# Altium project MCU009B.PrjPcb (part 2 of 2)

## Sheet MCU009B_Xds100v2Emu.SchDoc: Xds100v2Emu
size 431 x 279 mm; Date: Not shown in title block; ApprovedBy: Not shown in title block; CheckedBy: Not shown in title block; Author: Not shown in title block; CompanyName: Not shown in title block; Engineer: Not shown in title block; Organization: Not shown in title block; Address1: Not shown in title block; Address2: Not shown in title block; Address3: Not shown in title block; Address4: Not shown in title block; DocumentNumber: 5; Revision: Use project parameter SCH_Rev; SheetNumber: 5; SheetTotal: 7; PageSetup: Record=PageOptions¦CenterHorizontal=True¦CenterVertical=True¦PrintScale=1.00¦XCorrection=1.00¦YCorrection=1.00¦PrintKind=0¦BorderSize=5000000¦LeftOffset=0¦BottomOffset=0¦Orientation=2¦PaperLength=1000¦PaperWidth=1000¦Scale=100¦PaperSource=15¦PrintQuality=600¦MediaType=1¦DitherType=10¦PaperKind=Letter¦PrintScaleMode=1
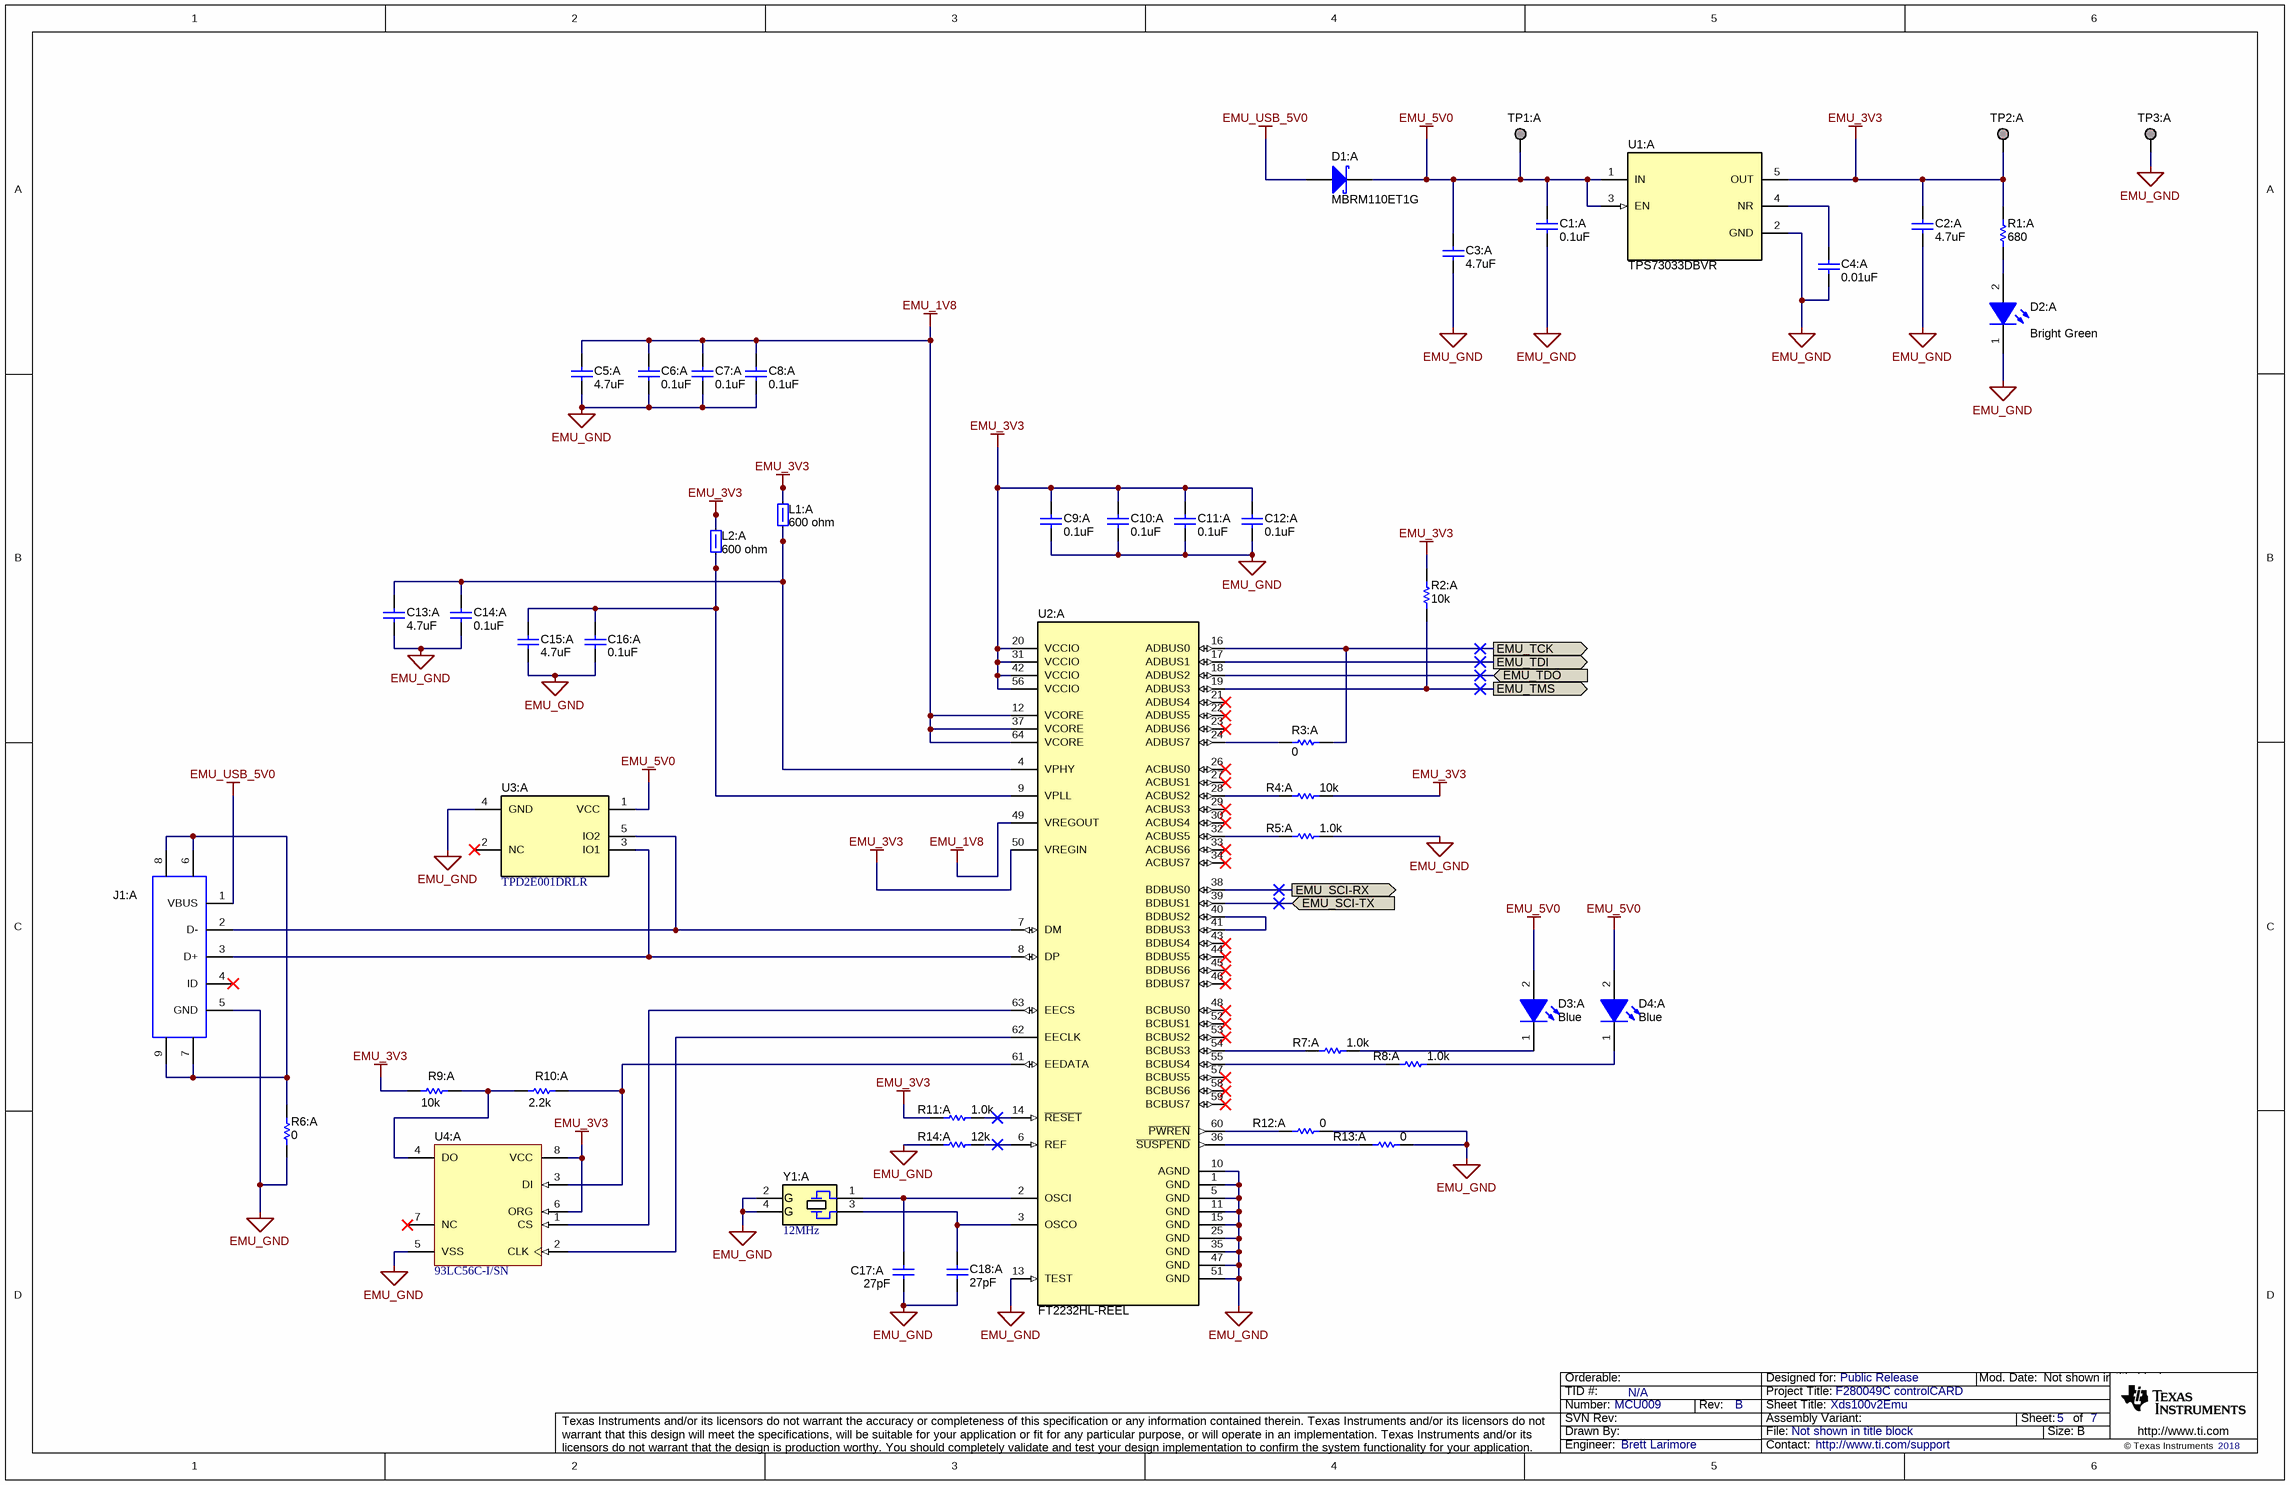
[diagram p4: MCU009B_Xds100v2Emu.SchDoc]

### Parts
C1:A  ValueDisplayed: 0.1uF  [0402]  (hidden comment: GRM155R71A104KA01D)
C2:A  ValueDisplayed: 4.7uF  [0603]  (hidden comment: GRM188R60J475ME19D)
C3:A  ValueDisplayed: 4.7uF  [0603]  (hidden comment: GRM188R60J475ME19D)
C4:A  ValueDisplayed: 0.01uF  [0402]  (hidden comment: GRM155R71C103KA01D)
C5:A  ValueDisplayed: 4.7uF  [0603]  (hidden comment: GRM188R60J475ME19D)
C6:A  ValueDisplayed: 0.1uF  [0402]  (hidden comment: GRM155R71A104KA01D)
C7:A  ValueDisplayed: 0.1uF  [0402]  (hidden comment: GRM155R71A104KA01D)
C8:A  ValueDisplayed: 0.1uF  [0402]  (hidden comment: GRM155R71A104KA01D)
C9:A  ValueDisplayed: 0.1uF  [0402]  (hidden comment: GRM155R71A104KA01D)
C10:A  ValueDisplayed: 0.1uF  [0402]  (hidden comment: GRM155R71A104KA01D)
C11:A  ValueDisplayed: 0.1uF  [0402]  (hidden comment: GRM155R71A104KA01D)
C12:A  ValueDisplayed: 0.1uF  [0402]  (hidden comment: GRM155R71A104KA01D)
C13:A  ValueDisplayed: 4.7uF  [0603]  (hidden comment: GRM188R60J475ME19D)
C14:A  ValueDisplayed: 0.1uF  [0402]  (hidden comment: GRM155R71A104KA01D)
C15:A  ValueDisplayed: 4.7uF  [0603]  (hidden comment: GRM188R60J475ME19D)
C16:A  ValueDisplayed: 0.1uF  [0402]  (hidden comment: GRM155R71A104KA01D)
C17:A  ValueDisplayed: 27pF  [0402]  (hidden comment: GRM1555C1H270JA01D)
C18:A  ValueDisplayed: 27pF  [0402]  (hidden comment: GRM1555C1H270JA01D)
D1:A  MBRM110ET1G  [POWERMITE]
D2:A  value Bright Green  [WL-SMCW_Green_0805]  (hidden comment: 150080VS75000)
D3:A  value Blue  [WL-SMCW_Blue_0805]  (hidden comment: 150080BS75000)
D4:A  value Blue  [WL-SMCW_Blue_0805]  (hidden comment: 150080BS75000)
J1:A  65100516121  [Wurth_65100516121]  (value not drawn)
L1:A  value 600 ohm  [0805_HV]  (hidden comment: HZ0805E601R-10)
L2:A  value 600 ohm  [0805_HV]  (hidden comment: HZ0805E601R-10)
R1:A  ValueDisplayed: 680  [0402]  (hidden comment: CRCW0402680RJNED)
R2:A  ValueDisplayed: 10k  [0402]  (hidden comment: CRCW040210K0JNED)
R3:A  ValueDisplayed: 0  [0402]  (hidden comment: CRCW04020000Z0ED)
R4:A  ValueDisplayed: 10k  [0402]  (hidden comment: CRCW040210K0JNED)
R5:A  ValueDisplayed: 1.0k  [0402]  (hidden comment: CRCW04021K00JNED)
R6:A  ValueDisplayed: 0  [0402]  (hidden comment: CRCW04020000Z0ED)
R7:A  ValueDisplayed: 1.0k  [0402]  (hidden comment: CRCW04021K00JNED)
R8:A  ValueDisplayed: 1.0k  [0402]  (hidden comment: CRCW04021K00JNED)
R9:A  ValueDisplayed: 10k  [0402]  (hidden comment: CRCW040210K0JNED)
R10:A  ValueDisplayed: 2.2k  [0402]  (hidden comment: CRCW04022K20JNED)
R11:A  ValueDisplayed: 1.0k  [0402]  (hidden comment: CRCW04021K00JNED)
R12:A  ValueDisplayed: 0  [0402]  (hidden comment: CRCW04020000Z0ED)
R13:A  ValueDisplayed: 0  [0402]  (hidden comment: CRCW04020000Z0ED)
R14:A  ValueDisplayed: 12k  [0402]  (hidden comment: CRCW040212K0JNED)
TP1:A  TESTPOINT  [TP_50MIL-25MILHOLE]  (value not drawn)  (no BOM)
TP2:A  TESTPOINT  [TP_50MIL-25MILHOLE]  (value not drawn)  (no BOM)
TP3:A  TESTPOINT  [TP_50MIL-25MILHOLE]  (value not drawn)  (no BOM)
U1:A  TPS73033DBVR  [DBV0005A_N]
U2:A  FT2232HL-REEL  [LQFP64_N]
U3:A  TPD2E001DRLR  [DRL0005A]
U4:A  93LC56C-I/SN  [SOIC-8]
Y1:A  12MHz  [ECS_ECX-53B]

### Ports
EMU_SCI-RX (out), EMU_SCI-TX (in), EMU_TCK (out), EMU_TDI (out), EMU_TDO (in), EMU_TMS (out)

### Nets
EMU_1V8: C5:A.2 C6:A.2 C7:A.2 C8:A.2 U2:A.12(VCORE) U2:A.37(VCORE) U2:A.49(VREGOUT) U2:A.64(VCORE)
EMU_3V3: C2:A.1 C9:A.2 C10:A.2 C11:A.2 C12:A.2 L1:A.2 L2:A.2 R1:A.1 R2:A.2 R4:A.2 R9:A.1 R11:A.1 TP2:A.1 U1:A.5(OUT) U2:A.20(VCCIO) U2:A.31(VCCIO) U2:A.42(VCCIO) U2:A.50(VREGIN) U2:A.56(VCCIO) U4:A.6(ORG) U4:A.8(VCC)
EMU_5V0: C1:A.2 C3:A.1 D1:A.1(K) D3:A.2(A) D4:A.2(A) TP1:A.1 U1:A.1(IN) U1:A.3(EN) U3:A.1(VCC)
EMU_GND: C1:A.1 C2:A.2 C3:A.2 C4:A.1 C5:A.1 C6:A.1 C7:A.1 C8:A.1 C9:A.1 C10:A.1 C11:A.1 C12:A.1 C13:A.2 C14:A.1 C15:A.2 C16:A.1 C17:A.1 C18:A.1 D2:A.1(K) J1:A.5(GND) R5:A.2 R6:A.2 R12:A.1 R13:A.1 R14:A.1 TP3:A.1 U1:A.2(GND) U2:A.1(GND) U2:A.5(GND) U2:A.10(AGND) U2:A.11(GND) U2:A.13(TEST) U2:A.15(GND) U2:A.25(GND) U2:A.35(GND) U2:A.47(GND) U2:A.51(GND) U3:A.4(GND) U4:A.5(VSS) Y1:A.2(GND) Y1:A.4(GND)
EMU_USB_5V0: D1:A.2(A) J1:A.1(VBUS)
EMU_SCI-RX: U2:A.38(BDBUS0) ; port EMU_SCI-RX
EMU_SCI-TX: U2:A.39(BDBUS1) ; port EMU_SCI-TX
EMU_TCK: R3:A.1 U2:A.16(ADBUS0) ; port EMU_TCK
EMU_TDI: U2:A.17(ADBUS1) ; port EMU_TDI
EMU_TDO: U2:A.18(ADBUS2) ; port EMU_TDO
EMU_TMS: R2:A.1 U2:A.19(ADBUS3) ; port EMU_TMS
NetC4:A_2: C4:A.2 U1:A.4(NR)
NetC13:A_1: C13:A.1 C14:A.2 L1:A.1 U2:A.4(VPHY)
NetC15:A_1: C15:A.1 C16:A.2 L2:A.1 U2:A.9(VPLL)
NetC17:A_2: C17:A.2 U2:A.2(OSCI) Y1:A.1
NetC18:A_2: C18:A.2 U2:A.3(OSCO) Y1:A.3
NetD2:A_2: D2:A.2(A) R1:A.2
NetD3:A_1: D3:A.1(K) R7:A.2
NetD4:A_1: D4:A.1(K) R8:A.2
NetJ1:A_2: J1:A.2(D-) U2:A.7(DM) U3:A.5(IO2)
NetJ1:A_3: J1:A.3(D+) U2:A.8(DP) U3:A.3(IO1)
NetJ1:A_6: J1:A.6 J1:A.7 J1:A.8 J1:A.9 R6:A.1
NetR3:A_2: R3:A.2 U2:A.24(ADBUS7)
NetR4:A_1: R4:A.1 U2:A.28(ACBUS2)
NetR5:A_1: R5:A.1 U2:A.32(ACBUS5)
NetR7:A_1: R7:A.1 U2:A.54(BCBUS3)
NetR8:A_1: R8:A.1 U2:A.55(BCBUS4)
NetR9:A_2: R9:A.2 R10:A.1 U4:A.4(DO)
NetR10:A_2: R10:A.2 U2:A.61(EEDATA) U4:A.3(DI)
NetR11:A_2: R11:A.2 U2:A.14(~{RESET})
NetR12:A_2: R12:A.2 U2:A.60(~{PWREN})
NetR13:A_2: R13:A.2 U2:A.36(~{SUSPEND})
NetR14:A_2: R14:A.2 U2:A.6(REF)
NetU2:A_40: U2:A.40(BDBUS2) U2:A.41(BDBUS3)
NetU2:A_62: U2:A.62(EECLK) U4:A.2(CLK)
NetU2:A_63: U2:A.63(EECS) U4:A.1(CS)

Not connected (* = marked no-connect by the designer): J1:A 4(ID)*; U2:A 21(ADBUS4)* 22(ADBUS5)* 23(ADBUS6)* 26(ACBUS0)* 27(ACBUS1)* 29(ACBUS3)* 30(ACBUS4)* 33(ACBUS6)* 34(ACBUS7)* 43(BDBUS4)* 44(BDBUS5)* 45(BDBUS6)* 46(BDBUS7)* 48(BCBUS0)* 52(BCBUS1)* 53(BCBUS2)* 57(BCBUS5)* 58(BCBUS6)* 59(BCBUS7)*; U3:A 2(NC)*; U4:A 7(NC)*

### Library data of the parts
C1:A C6:A C7:A C8:A C9:A C10:A C11:A C12:A C14:A C16:A = CMP-0006629-2: CAP, CERM, 0.1 uF, 10 V, +/- 10%, X7R, 0402; Manufacturer: MuRata; Polarized: N; Value: 0.1uF; U/M: EA; Cap_F: 100nF; Value1: Unknown; VDC_V: 10V; TaMin_C: -55°C; TaMax_C: 125°C; AEC Category: Q200; SizeArea_mm2: 0.5; SizeAreaWB_mm2: 3; SizeX_mm: 1; SizeZ_mm: 0.6
C2:A C3:A C5:A C13:A C15:A = CMP-0007312-5: CAP, CERM, 4.7 uF, 6.3 V, +/- 20%, X5R, 0603; Manufacturer: MuRata; Polarized: N; Value: 4.7uF; U/M: EA; Cap_F: 4.7µF; ESR_ohm: 1m; Value1: 0.001 ohm; VDC_V: 6.3V; TaMin_C: -55°C; TaMax_C: 85°C; AEC Category: Q200; SizeArea_mm2: 1.28; SizeAreaWB_mm2: 4.68; SizeX_mm: 1.6; SizeY_mm: 0.8; SizeZ_mm: 1
C4:A = CMP-0006639-2: CAP, CERM, 0.01 uF, 16 V, +/- 10%, X7R, 0402; Manufacturer: MuRata; Polarized: N; Value: 0.01uF; U/M: EA; Cap_F: 10nF; Value1: Unknown; VDC_V: 16V; TaMin_C: -55°C; TaMax_C: 125°C; AEC Category: Q200; SizeArea_mm2: 0.5; SizeAreaWB_mm2: 3; SizeX_mm: 1; SizeZ_mm: 0.6
C17:A C18:A = CMP-0006443-2: CAP, CERM, 27 pF, 50 V, +/- 5%, C0G/NP0, 0402; Manufacturer: MuRata; Polarized: N; Value: 27pF; U/M: EA; Value1: Unknown; VDC_V: 50V; TaMin_C: -55°C; TaMax_C: 125°C; AEC Category: Q200; SizeArea_mm2: 0.5; SizeAreaWB_mm2: 3; SizeX_mm: 1; SizeZ_mm: 0.6
D1:A = CMP-0028747-1: Diode, Schottky, 10 V, 1 A, AEC-Q101, POWERMITE; Manufacturer: ON Semiconductor; U/M: EA; Vf_V: 5.3dV; Value: 10V; Value1: 1A; Value2: 0.53V; TJmax_C: 150°C; AEC Category: Q101; AEC Qualified: Y; SizeAreaWB_mm2: 14.945; SizeArea_mm2: 7.995; SizeX_mm: 3.9; SizeY_mm: 2.05; SizeZ_mm: 1.15; Green_Lifecycle: Not Set; Green_REACh: Incomplete
D2:A = CMP-0002960-2: LED, Bright Green, SMD; Manufacturer: Wurth Elektronik; Type: AlInGaP; Vf_V: 2V; Io_A: 20mA; Vr_V: 5V; Tjmax_C: 85°C; Power_TotalModule: 72mW; Value1: 0.072W; Angle: 140; U/M: EA
D3:A D4:A = CMP-0002959-2: LED, Blue, SMD; Manufacturer: Wurth Elektronik; Type: InGaN; Vf_V: 3.2V; Io_A: 20mA; Vr_V: 5V; Tjmax_C: 85°C; Power_TotalModule: 105mW; Value1: 0.105W; Angle: 140; U/M: EA
J1:A = CMP-0054809-1: Connector, Receptacle, USB Mini B 2.0, SMT; Manufacturer: Wurth Elektronik; Pitch_mm: 0.8; Gender: Female; Row_Count: 1; ContactFinish: Gold; Current_A: 1A; Voltage_V: 30V; Cert_UL: Y; CNHeader: FALSE; CT: TRUE; Green_Lifecycle: Active; Green_REACh: Passed
L1:A L2:A = CMP-0003398-1: Ferrite Bead, 600 ohm @ 100 MHz, 0.5 A, 0805; Manufacturer: Laird-Signal Integrity Products; Imax_A: 5dA; DCR_ohm: 3d; Value1: 0.3 ohm; Value2: 0.5A; ZTyp@100MHz_Ohm: 600; SizeArea_mm2: 2.5; SizeAreaWB_mm2: 6.75; SizeX_mm: 2; SizeY_mm: 1.25; SizeZ_mm: 1.45
R1:A = CMP-0026962-3: RES, 680, 5%, 0.063 W, AEC-Q200 Grade 0, 0402; Manufacturer: Vishay-Dale; Value: 680; Value_Code: 680R; Power_W: 63mW; Value2: 0.063W; VDC_V: 50V; TempCo: 200 ppm/C; EIA_Code: E24; AEC Category: Q200; AEC Qualified: Y; AEC Grade: 0; SizeArea_mm2: 0.5; SizeX_mm: 1; SizeZ_mm: 0.6
R2:A R4:A R9:A = CMP-0026825-5: RES, 10 k, 5%, 0.063 W, AEC-Q200 Grade 0, 0402; Manufacturer: Vishay-Dale; Value: 10k; Value_Code: 10k0; Power_W: 63mW; Value2: 0.063W; VDC_V: 50V; TempCo: 200 ppm/C; EIA_Code: E24; AEC Category: Q200; AEC Qualified: Y; AEC Grade: 0; SizeArea_mm2: 0.5; SizeX_mm: 1; SizeZ_mm: 0.6
R3:A R6:A R12:A R13:A = CMP-0026822-3: RES, 0, 5%, 0.063 W, AEC-Q200 Grade 0, 0402; Manufacturer: Vishay-Dale; Value: 0; Value_Code: 0000; Power_W: 63mW; Value2: 0.063W; VDC_V: 50V; TempCo: 200 ppm/C; EIA_Code: E24; AEC Category: Q200; AEC Qualified: Y; SizeArea_mm2: 0.5; SizeX_mm: 1; SizeZ_mm: 0.6
R5:A R7:A R8:A R11:A = CMP-0026852-3: RES, 1.0 k, 5%, 0.063 W, AEC-Q200 Grade 0, 0402; Manufacturer: Vishay-Dale; Value: 1.0k; Res_ohm: 1k; Value_Code: 1k00; Power_W: 63mW; Value2: 0.063W; VDC_V: 50V; TempCo: 200 ppm/C; EIA_Code: E24; AEC Category: Q200; AEC Qualified: Y; AEC Grade: 0; SizeArea_mm2: 0.5; SizeX_mm: 1; SizeZ_mm: 0.6
R10:A = CMP-0026890-5: RES, 2.2 k, 5%, 0.063 W, AEC-Q200 Grade 0, 0402; Manufacturer: Vishay-Dale; Value: 2.2k; Value_Code: 2k20; Power_W: 63mW; Value2: 0.063W; VDC_V: 50V; TempCo: 200 ppm/C; EIA_Code: E24; AEC Category: Q200; AEC Qualified: Y; AEC Grade: 0; SizeArea_mm2: 0.5; SizeX_mm: 1; SizeZ_mm: 0.6
R14:A = CMP-0026834-3: RES, 12 k, 5%, 0.063 W, AEC-Q200 Grade 0, 0402; Manufacturer: Vishay-Dale; Value: 12k; Value_Code: 12k0; Power_W: 63mW; Value2: 0.063W; VDC_V: 50V; TempCo: 200 ppm/C; EIA_Code: E24; AEC Category: Q200; AEC Qualified: Y; AEC Grade: 0; SizeArea_mm2: 0.5; SizeX_mm: 1; SizeZ_mm: 0.6
TP1:A TP2:A TP3:A = CMP-0078143-2: TEST POINT.  No entry in BOM.
U1:A = CMP-0073823-1: Low-Noise, High PSRR, RF 200-mA Low-Dropout Linear Regulators, DBV0005A (SOT-23-5); Alternate PartNumber: TPS73033DBVT; Manufacturer: Texas Instruments; CompType: IC; U/M: EA; SizeArea_mm2: 8.12; SizeAreaWB_mm2: 14.82; SizeX_mm: 2.8; SizeY_mm: 2.9; SizeZ_mm: 1.45; Green_Lifecycle: Active; Green_REACh: Passed
U2:A = CMP-0004796-1: Dual High Speed USB To Multipurpose UART/FIFO IC, LQFP-64; Manufacturer: FTDI
U3:A = CMP-0043096-2: Low-Capacitance + / - 15 kV ESD-Protection Array for High-Speed Data Interfaces, 2 Channels, -40 to +85 degC, 5-pin SOT (DRL), Green (RoHS & no Sb/Br); Manufacturer: Texas Instruments; Breakdown Voltage(Min)(V): 11; IEC 61000-4-2 Air-Gap(+/- kV): 15; IEC 61000-4-2 Contact(+/- kV): 8; IO Capacitance(Typ)(pF): 1.5; IO Leakage Current(nA): 1; SubFamily: ESD Solution; USB High Speed: TRUE
U4:A = CMP-0005261-2: 2K Microwire Compatible Serial EEPROM, SOIC-8; Manufacturer: Microchip; SizeAreaWB_mm2: 55.131; SizeArea_mm2: 29.351; SizeX_mm: 5.99; SizeY_mm: 4.9; SizeZ_mm: 1.75
Y1:A = CMP-0004646-3: Crystal, 12 MHz, 20pF, SMD; PartNumber: ECS-120-20-30B-TR; Manufacturer: ECS Inc.; TaMin_C: -20°C; TaMax_C: 70°C; Frequency Stability: +/-50ppm

## Sheet MCU009B_EVM_Hardware.SchDoc: EVM Hardware
size 431 x 279 mm; Date: Not shown in title block; ApprovedBy: Not shown in title block; CheckedBy: Not shown in title block; Author: Not shown in title block; CompanyName: Not shown in title block; Engineer: Not shown in title block; Organization: Not shown in title block; Address1: Not shown in title block; Address2: Not shown in title block; Address3: Not shown in title block; Address4: Not shown in title block; DocumentNumber: 7; Revision: Use project parameter SCH_Rev; SheetNumber: 7; SheetTotal: 7; PageSetup: Record=PageOptions¦CenterHorizontal=True¦CenterVertical=True¦PrintScale=1.00¦XCorrection=1.00¦YCorrection=1.00¦PrintKind=0¦BorderSize=5000000¦LeftOffset=0¦BottomOffset=0¦Orientation=2¦PaperLength=1000¦PaperWidth=1000¦Scale=100¦PaperSource=15¦PrintQuality=600¦MediaType=1¦DitherType=10¦PaperKind=Letter¦PrintScaleMode=1
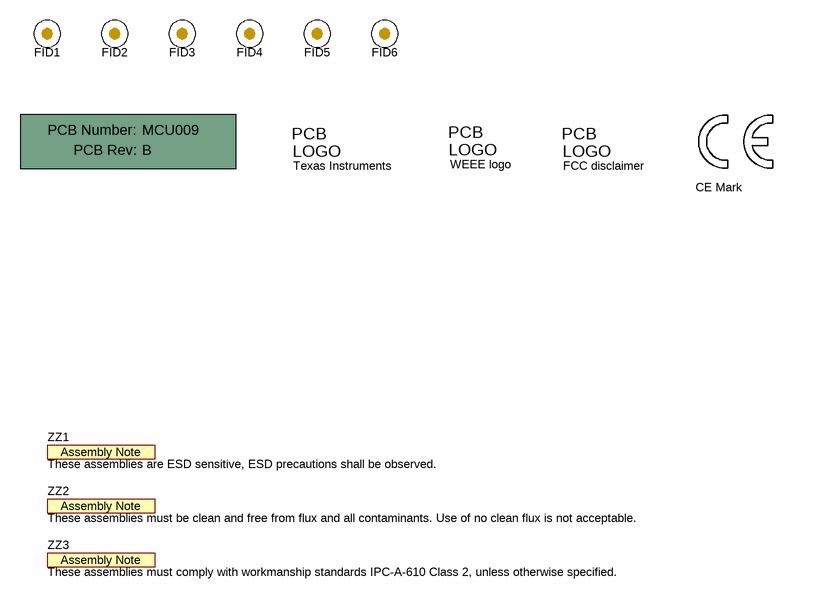
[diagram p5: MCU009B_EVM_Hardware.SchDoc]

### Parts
!PCB1  Printed Circuit Board  (value not drawn)  (mechanical)
FID1  Fiducial  [Fiducial10-20]  (value not drawn)
FID2  Fiducial  [Fiducial10-20]  (value not drawn)
FID3  Fiducial  [Fiducial10-20]  (value not drawn)
FID4  Fiducial  [Fiducial10-20]  (value not drawn)
FID5  Fiducial  [Fiducial10-20]  (value not drawn)
FID6  Fiducial  [Fiducial10-20]  (value not drawn)
Logo1  Texas Instruments  [TI_Symbol_Overlay_Small]  (no BOM)
Logo2  WEEE logo  [WEEE_Minimum]  (no BOM)
Logo3  FCC disclaimer  [FCC_disclaimer]  (no BOM)
LOGO4  CE Mark  [CE_Mark_5mm]  (no BOM)
ZZ1  These assemblies are ESD sensitive, ESD precautions shall be observed.  [AssemblyNote]  (no BOM)
ZZ2  These assemblies must be clean and free from flux and all contaminants. Use of no clean flux is not acceptable.  [AssemblyNote]  (no BOM)
ZZ3  These assemblies must comply with workmanship standards IPC-A-610 Class 2, unless otherwise specified.  [AssemblyNote]  (no BOM)

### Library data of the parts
!PCB1 = CMP-0003618-2: Manufacturer: Any; PartNumber: MCU009
FID1-FID6 = CMP-0077181-1: Fiducial mark.  There is nothing to buy or mount.
Logo1 = CMP-0074838-1: Texas Instrument Corporate Signature; SymbolCreator: a0412235; Lib Reference: TI_Logo
Logo2 = CMP-0074769-1
Logo3 = CMP-0074847-1: FCC_disclaimer
LOGO4 = CMP-0074844-1: SymbolCreator: a0412235
ZZ1 = CMP-0077236-1
ZZ2 = CMP-0077237-1
ZZ3 = CMP-0077238-1

## Sheet MCU009B_EmuInterface.SchDoc: EmuInterface
size 431 x 279 mm; Date: Not shown in title block; ApprovedBy: Not shown in title block; CheckedBy: Not shown in title block; Author: Not shown in title block; CompanyName: Not shown in title block; Engineer: Not shown in title block; Organization: Not shown in title block; Address1: Not shown in title block; Address2: Not shown in title block; Address3: Not shown in title block; Address4: Not shown in title block; DocumentNumber: 6; Revision: Use project parameter SCH_Rev; SheetNumber: 6; SheetTotal: 7; PageSetup: Record=PageOptions¦CenterHorizontal=True¦CenterVertical=True¦PrintScale=1.00¦XCorrection=1.00¦YCorrection=1.00¦PrintKind=0¦BorderSize=5000000¦LeftOffset=0¦BottomOffset=0¦Orientation=2¦PaperLength=1000¦PaperWidth=1000¦Scale=100¦PaperSource=15¦PrintQuality=600¦MediaType=1¦DitherType=10¦PaperKind=Letter¦PrintScaleMode=1
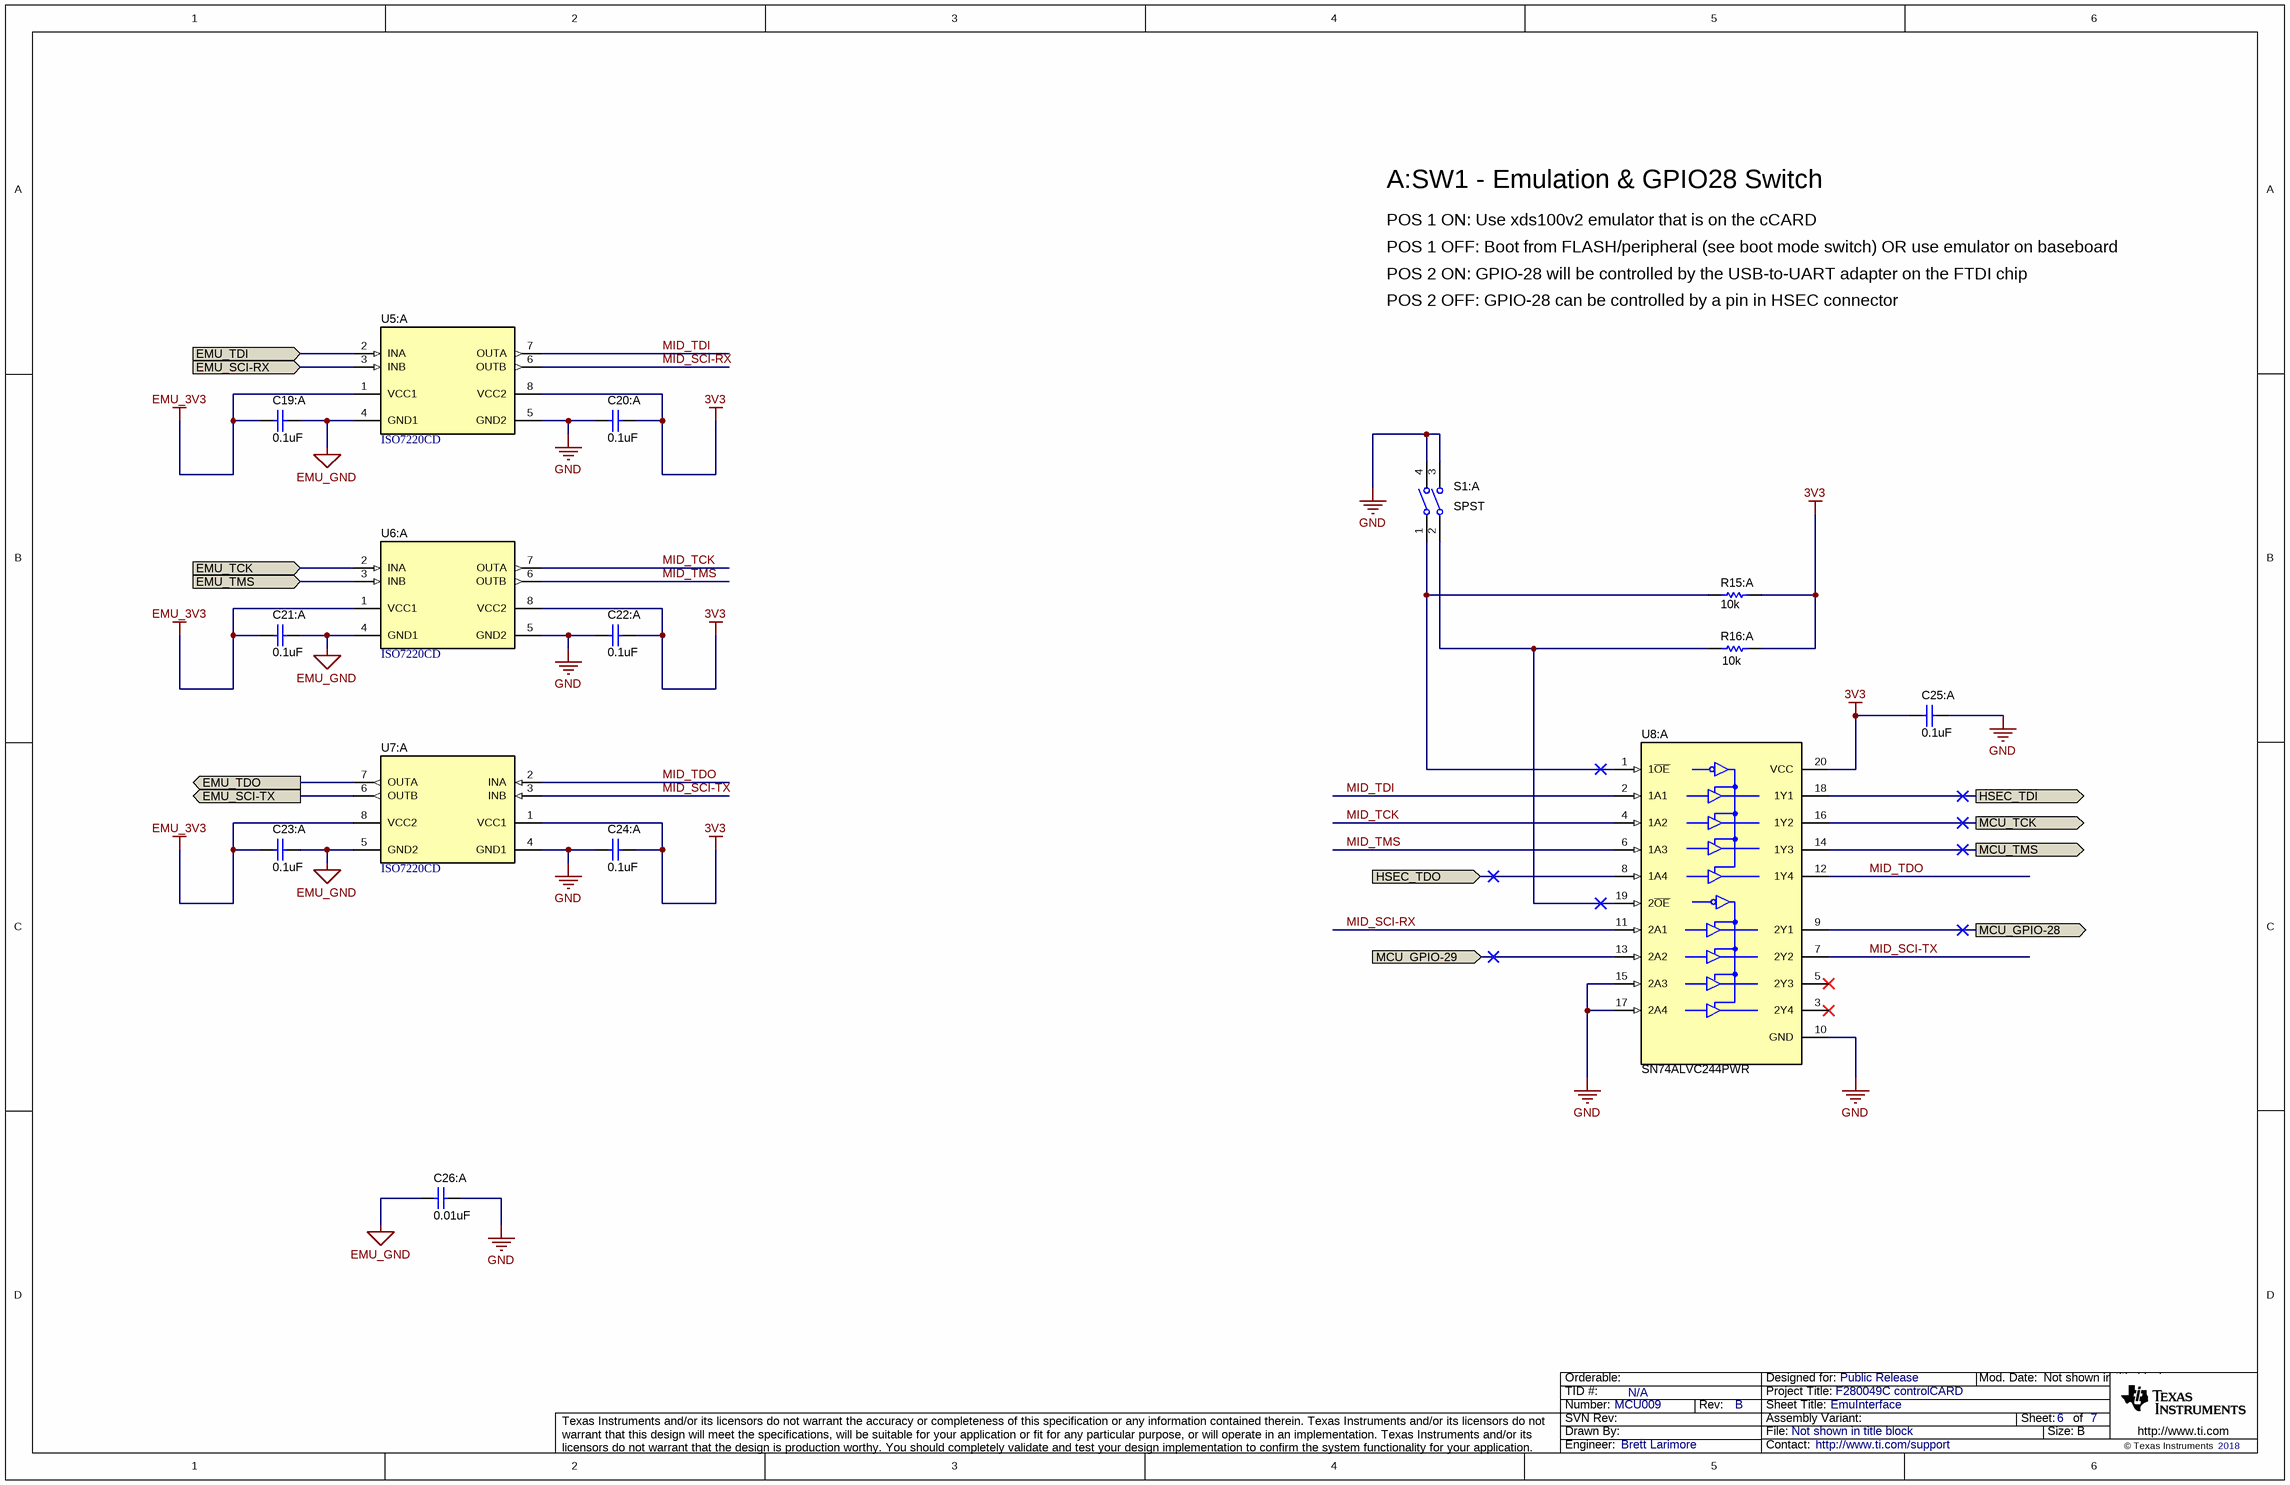
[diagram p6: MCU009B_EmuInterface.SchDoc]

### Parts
C19:A  ValueDisplayed: 0.1uF  [0402]  (hidden comment: GRM155R71A104KA01D)
C20:A  ValueDisplayed: 0.1uF  [0402]  (hidden comment: GRM155R71A104KA01D)
C21:A  ValueDisplayed: 0.1uF  [0402]  (hidden comment: GRM155R71A104KA01D)
C22:A  ValueDisplayed: 0.1uF  [0402]  (hidden comment: GRM155R71A104KA01D)
C23:A  ValueDisplayed: 0.1uF  [0402]  (hidden comment: GRM155R71A104KA01D)
C24:A  ValueDisplayed: 0.1uF  [0402]  (hidden comment: GRM155R71A104KA01D)
C25:A  ValueDisplayed: 0.1uF  [0402]  (hidden comment: GRM155R71A104KA01D)
C26:A  ValueDisplayed: 0.01uF  [1812]  (hidden comment: 1812SC103KAT1A)
R15:A  ValueDisplayed: 10k  [0402]  (hidden comment: CRCW040210K0JNED)
R16:A  ValueDisplayed: 10k  [0402]  (hidden comment: CRCW040210K0JNED)
S1:A  Circuit: SPST  [SW_218-2LP]  (hidden comment: 218-2LPST)
U5:A  ISO7220CD  [D0008B_N]
U6:A  ISO7220CD  [D0008B_N]
U7:A  ISO7220CD  [D0008B_N]
U8:A  SN74ALVC244PWR  [PW0020A_N]

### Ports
EMU_SCI-RX (in), EMU_SCI-TX (out), EMU_TCK (in), EMU_TDI (in), EMU_TDO (out), EMU_TMS (in), HSEC_TDI (out), HSEC_TDO (in), MCU_GPIO-28 (out), MCU_GPIO-29 (in), MCU_TCK (out), MCU_TMS (out)

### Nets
3V3: C20:A.1 C22:A.1 C24:A.1 C25:A.2 R15:A.2 R16:A.2 U5:A.8(VCC2) U6:A.8(VCC2) U7:A.1(VCC1) U8:A.20(VCC)
EMU_3V3: C19:A.2 C21:A.2 C23:A.2 U5:A.1(VCC1) U6:A.1(VCC1) U7:A.8(VCC2)
EMU_GND: C19:A.1 C21:A.1 C23:A.1 C26:A.2 U5:A.4(GND1) U6:A.4(GND1) U7:A.5(GND2)
GND: C20:A.2 C22:A.2 C24:A.2 C25:A.1 C26:A.1 S1:A.3 S1:A.4 U5:A.5(GND2) U6:A.5(GND2) U7:A.4(GND1) U8:A.10(GND) U8:A.15(2A3) U8:A.17(2A4)
EMU_SCI-RX: U5:A.3(INB) ; port EMU_SCI-RX
EMU_SCI-TX: U7:A.6(OUTB) ; port EMU_SCI-TX
EMU_TCK: U6:A.2(INA) ; port EMU_TCK
EMU_TDI: U5:A.2(INA) ; port EMU_TDI
EMU_TDO: U7:A.7(OUTA) ; port EMU_TDO
EMU_TMS: U6:A.3(INB) ; port EMU_TMS
HSEC_TDI: U8:A.18(1Y1) ; port HSEC_TDI
HSEC_TDO: U8:A.8(1A4) ; port HSEC_TDO
MCU_GPIO-28: U8:A.9(2Y1) ; port MCU_GPIO-28
MCU_GPIO-29: U8:A.13(2A2) ; port MCU_GPIO-29
MCU_TCK: U8:A.16(1Y2) ; port MCU_TCK
MCU_TMS: U8:A.14(1Y3) ; port MCU_TMS
MID_SCI-RX: U5:A.6(OUTB) U8:A.11(2A1)
MID_SCI-TX: U7:A.3(INB) U8:A.7(2Y2)
MID_TCK: U6:A.7(OUTA) U8:A.4(1A2)
MID_TDI: U5:A.7(OUTA) U8:A.2(1A1)
MID_TDO: U7:A.2(INA) U8:A.12(1Y4)
MID_TMS: U6:A.6(OUTB) U8:A.6(1A3)
NetR15:A_1: R15:A.1 S1:A.1 U8:A.1(1~{OE})
NetR16:A_1: R16:A.1 S1:A.2 U8:A.19(2~{OE})

Not connected (* = marked no-connect by the designer): U8:A 3(2Y4)* 5(2Y3)*

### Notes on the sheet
- A:SW1 - Emulation & GPIO28 Switch
- POS 1 ON: Use xds100v2 emulator that is on the cCARD
- POS 1 OFF: Boot from FLASH/peripheral (see boot mode switch) OR use emulator on baseboard
- POS 2 ON: GPIO-28 will be controlled by the USB-to-UART adapter on the FTDI chip
- POS 2 OFF: GPIO-28 can be controlled by a pin in HSEC connector

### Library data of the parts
C19:A C20:A C21:A C22:A C23:A C24:A C25:A = CMP-0006629-2: as C1:A on sheet MCU009B_Xds100v2Emu
C26:A = CMP-0009297-2: CAP, CERM, 0.01 uF, 1500 V, +/- 10%, X7R, 1812; Manufacturer: AVX; Polarized: N; Value: 0.01uF; U/M: EA; Cap_F: 10nF; ESR_ohm: 0.05; Value1: 0.05 ohm; VDC_V: 1.5kV; Value2: 1500V; TaMin_C: -55°C; TaMax_C: 125°C; AEC Category: Q200; SizeArea_mm2: 14.4; SizeAreaWB_mm2: 23.1; SizeX_mm: 4.5; SizeY_mm: 3.2; SizeZ_mm: 1.35
R15:A R16:A = CMP-0026825-5: as R2:A on sheet MCU009B_Xds100v2Emu
S1:A = CMP-0002230-1: Switch, SPST, 2 Pos, 25mA, 24VDC, SMD; Manufacturer: CTS Electrocomponents; VDC_V: 24V; SwitchFunction: Off-On; PositionCount: 2; CurrentRating_mA: 25A
U5:A U6:A U7:A = CMP-0029375-1: 25 Mbps Dual Channels, 2 / 0, Digital Isolator, 3.3 V / 5 V, -40 to +125 degC, 8-pin SOIC (D), Green (RoHS & no Sb/Br); Manufacturer: Texas Instruments; Datarate(Mbps): 25; Input Noise Filter: Yes; Insulation Rating(VRMS): 2500; Prop Delay(Max)(ns): 42; Rating: Catalog; Supply Voltage(s)(V): 3.3, 5; TTL/CMOS Input Threshold: TTL
U8:A = CMP-0047070-3: Octal Buffer/Driver With 3-State OUtputs, PW0020A (TSSOP-20); Manufacturer: Texas Instruments; Bits(#): 8; F @ Nom Voltage(Max)(Mhz): 100; ICC @ Nom Voltage(Max)(mA): 0.024; Input Type: LVTTL; Rating: Catalog; tpd @ Nom Voltage(Max)(ns): 4.4,3.1,2.8; VCC(Max)(V): 3.6; VCC(Min)(V): 1.65; Voltage(Nom)(V): 1.8,2.5,2.7,3.3; AEC Category: Q200; AEC Qualified: N; CompType: IC; SizeArea_mm2: 43.56; SizeAreaWB_mm2: 73.96; SizeX_mm: 6.6; SizeZ_mm: 1.2

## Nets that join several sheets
3V3: MCU009B_Connector+IO (R1.1 R2.2 R8.2 R9.2), MCU009B_Power+Misc (24 pins), MCU009B_EmuInterface (10 pins)
EMU_3V3: MCU009B_Xds100v2Emu (21 pins), MCU009B_EmuInterface (6 pins)
EMU_GND: MCU009B_Xds100v2Emu (41 pins), MCU009B_EmuInterface (7 pins)
GND: MCU009B_Connector+IO (12 pins), MCU009B_Power+Misc (45 pins), MCU009B_ADC (42 pins), MCU009B_EmuInterface (13 pins)
HSEC_5V0: MCU009B_Connector+IO (EC1.48 EC1.84 EC1.98 EC1.112), MCU009B_Power+Misc (5 pins)
MCU_A_3V3: MCU009B_Power+Misc (6 pins), MCU009B_ADC (7 pins)
EMU_SCI-RX: MCU009B_Xds100v2Emu (U2:A.38), MCU009B_EmuInterface (U5:A.3)
EMU_SCI-TX: MCU009B_Xds100v2Emu (U2:A.39), MCU009B_EmuInterface (U7:A.6)
EMU_TCK: MCU009B_Xds100v2Emu (R3:A.1 U2:A.16), MCU009B_EmuInterface (U6:A.2)
EMU_TDI: MCU009B_Xds100v2Emu (U2:A.17), MCU009B_EmuInterface (U5:A.2)
EMU_TDO: MCU009B_Xds100v2Emu (U2:A.18), MCU009B_EmuInterface (U7:A.7)
EMU_TMS: MCU009B_Xds100v2Emu (R2:A.1 U2:A.19), MCU009B_EmuInterface (U6:A.3)
HSEC_ADC-A0,B15,C15,DACA: MCU009B_Connector+IO (EC1.9), MCU009B_ADC (R36.2 U5.1)
HSEC_ADC-A1,DACB: MCU009B_Connector+IO (EC1.11), MCU009B_ADC (R38.2 U5.3)
HSEC_ADC-A2,B6,PGA1_IN: MCU009B_Connector+IO (EC1.15), MCU009B_ADC (R37.1 U6.1)
HSEC_ADC-A3: MCU009B_Connector+IO (EC1.17), MCU009B_ADC (R41.2 U5.4)
HSEC_ADC-A4,B8,PGA2_IN: MCU009B_Connector+IO (EC1.21), MCU009B_ADC (R39.1 U6.3)
HSEC_ADC-A5: MCU009B_Connector+IO (EC1.23), MCU009B_ADC (R44.2 U5.6)
HSEC_ADC-A6,PGA5_IN: MCU009B_Connector+IO (EC1.25), MCU009B_ADC (R43.1 U8.1)
HSEC_ADC-A8,PGA6_OF: MCU009B_Connector+IO (EC1.33), MCU009B_ADC (R35.1 U8.3)
HSEC_ADC-A9: MCU009B_Connector+IO (EC1.27), MCU009B_ADC (R47.2 U7.1)
HSEC_ADC-B0: MCU009B_Connector+IO (EC1.12), MCU009B_ADC (R49.2 U7.3)
HSEC_ADC-B1,A10,C10,PGA7_IN: MCU009B_Connector+IO (EC1.14), MCU009B_ADC (R46.1 U8.6)
HSEC_ADC-B2,C6,PGA3_IN: MCU009B_Connector+IO (EC1.18), MCU009B_ADC (R40.1 U6.4)
HSEC_ADC-B3,VDAC: MCU009B_Connector+IO (EC1.20), MCU009B_ADC (R53.2 U7.4)
HSEC_ADC-B4,C8,C3,PGA4_IN: MCU009B_Connector+IO (EC1.24), MCU009B_ADC (R42.1 U6.6)
HSEC_ADC-C0: MCU009B_Connector+IO (EC1.26), MCU009B_ADC (R60.2 U7.6)
HSEC_ADC-C1: MCU009B_Connector+IO (EC1.28), MCU009B_ADC (R61.2 U9.1)
HSEC_ADC-C2: MCU009B_Connector+IO (EC1.30), MCU009B_ADC (R62.2 U9.3)
HSEC_ADC-C4: MCU009B_Connector+IO (EC1.34), MCU009B_ADC (R63.2 U9.4)
HSEC_ADC-C5,PGA6_IN: MCU009B_Connector+IO (EC1.31), MCU009B_ADC (R45.1 U8.4)
HSEC_ADC-C14: MCU009B_Connector+IO (EC1.36), MCU009B_ADC (R64.2 U9.6)
HSEC_ADCVREFHI-Ext: MCU009B_Connector+IO (EC1.45), MCU009B_ADC (S8.1 S8.2)
HSEC_GPIO-22: MCU009B_Connector+IO (EC1.72), MCU009B_Power+Misc (R19.2)
HSEC_GPIO-23: MCU009B_Connector+IO (EC1.64), MCU009B_Power+Misc (R18.2)
HSEC_PGA1_GND: MCU009B_Connector+IO (EC1.13), MCU009B_ADC (R48.1)
HSEC_PGA3_GND: MCU009B_Connector+IO (EC1.16), MCU009B_ADC (R50.1)
HSEC_PGA5_GND: MCU009B_Connector+IO (EC1.29), MCU009B_ADC (R51.1)
HSEC_PGA7_GND: MCU009B_Connector+IO (EC1.10), MCU009B_ADC (R54.1)
HSEC_PGA246_GND: MCU009B_Connector+IO (EC1.19 EC1.22 EC1.35), MCU009B_ADC (R52.1)
HSEC_TDI: MCU009B_Connector+IO (EC1.8 R8.1 S4.3), MCU009B_EmuInterface (U8:A.18)
HSEC_TDO: MCU009B_Connector+IO (EC1.6 R9.1 S4.6), MCU009B_EmuInterface (U8:A.8)
MCU_GPIO-18: MCU009B_Connector+IO (R7.2 U1#1.68), MCU009B_Power+Misc (R16.2)
MCU_GPIO-22: MCU009B_Connector+IO (U1#1.83), MCU009B_Power+Misc (L3.2 R19.1 R22.2)
MCU_GPIO-23: MCU009B_Connector+IO (U1#1.81), MCU009B_Power+Misc (R18.1 R21.2 R24.2)
MCU_GPIO-24: MCU009B_Connector+IO (S5.2 U1#1.56), MCU009B_Power+Misc (R25.2 S1.2)
MCU_GPIO-28: MCU009B_Connector+IO (EC1.76 U1#1.1), MCU009B_EmuInterface (U8:A.9)
MCU_GPIO-29: MCU009B_Connector+IO (EC1.78 U1#1.100), MCU009B_EmuInterface (U8:A.13)
MCU_GPIO-31: MCU009B_Connector+IO (EC1.74 U1#1.99), MCU009B_Power+Misc (R12.1 U2.1)
MCU_GPIO-32: MCU009B_Connector+IO (EC1.82 U1#1.64), MCU009B_Power+Misc (R26.1 S1.1)
MCU_GPIO-34: MCU009B_Connector+IO (EC1.86 U1#1.94), MCU009B_Power+Misc (R13.1 U2.3)
MCU_TCK: MCU009B_Connector+IO (EC1.5), MCU009B_Power+Misc (U1#1.60), MCU009B_EmuInterface (U8:A.16)
MCU_TMS: MCU009B_Connector+IO (EC1.3), MCU009B_Power+Misc (R31.1 U1#1.62), MCU009B_EmuInterface (U8:A.14)
MCU_XRSn: MCU009B_Connector+IO (EC1.120), MCU009B_Power+Misc (5 pins)

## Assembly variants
001: not fitted C19 C20 C21 C28 C41 C42 C43 C44 C45 C46 C47 C48 C49 C50 C51 C52 C53 C54 C55 C56 C57 C58 C59 FID1 FID2 FID3 FID4 FID5 FID6 R7 R12:A R13:A R17 R21 R22 R24 R28 R55 R56 R57 R58 R59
